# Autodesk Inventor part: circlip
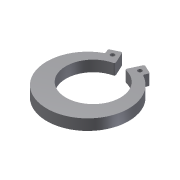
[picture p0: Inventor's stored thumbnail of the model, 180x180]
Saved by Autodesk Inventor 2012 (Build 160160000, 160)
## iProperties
Created: 2008-06
Part Number: circlip
Document SubType Name: Modeling
Designer: CADCIM
Density: 1 g/cm^3
Material: Default
Author: CADCIM
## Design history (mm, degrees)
sketch "Sketch1"
  geometry: L1 (-34.277, -4)-(34.277, -4); L2 (0, 41.942)-(0, -37.008); L3 (-3.5, 19.691)-(-8.149, 29.661); L4 (-8.149, 29.661)-(-15.399, 26.28); L5 (-15.399, 26.28)-(-13.72, 22.679); L6 (3.5, 19.691)-(8.149, 29.661); L7 (8.149, 29.661)-(15.399, 26.28); L8 (15.399, 26.28)-(13.72, 22.679); C1 r 1.5 at (-10.047, 24.267); C2 r 1.5 at (10.047, 24.267); A1 r 20 centre (0, 0) between (-3.5, 19.691) and (3.5, 19.691); A2 r 30 centre (0, -4) between (-13.72, 22.679) and (13.72, 22.679); 1 further point
  constraints: 16 end point, 5 point on circle, 5 symmetric about line, 4 centre point, 3 perpendicular, 2 midpoint, 2 point on line, 1 coincident, 1 horizontal, 2 other
  dimensions: "d0" = 40 diameter of A1; "d1" = 4 distance from line of L1 point (0, 0); "d2" = 60 diameter of A2; "d3" = 3 diameter of C1; "d16" = 8 distance of L3.end L4.end; "d17" = 11 distance of L6.start L6.end; "d20" = 4 distance from line of L3 C1.centre; "d21" = 50 deg angle of L3 L6; "d23" = 7 distance of L6.start L3.start
extrude "Extrusion1" new body sketch "Sketch1" distance "d5" = 8; taper "d6" = 0 deg
fillet "Fillet1" dims "d7" = 1
body "Solid1"
other parameters: "d13" = 0
